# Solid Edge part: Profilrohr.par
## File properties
Username: ahadarics
Dokumentum tartalom típus: 0
Author: ahadarics
Last saved by: ahadarics
Revision: 78
Sűrűség: 0,000 kg/m^3
Pontosság: 0,990
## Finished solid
Body 1: solid body, 91 faces, 266 edges, 176 vertices.
  Faces by surface: plane 46, cylinder 45
  Edges by curve: line 176, circle 90
Bounding box of the edges (mm): 49.000 x 49.000 x 30.800, from (-24.5, -24.5, 0) to (24.5, 24.5, 30.8).
Cylindrical faces by radius (mm): R0.15 x20, R0.25 x20, R8 x4, R16 x1
Planar faces by outward normal: +x 11, +y 11, +z 1, -x 11, -y 11, -z 1
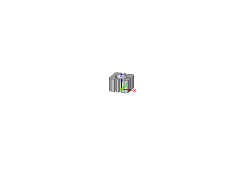
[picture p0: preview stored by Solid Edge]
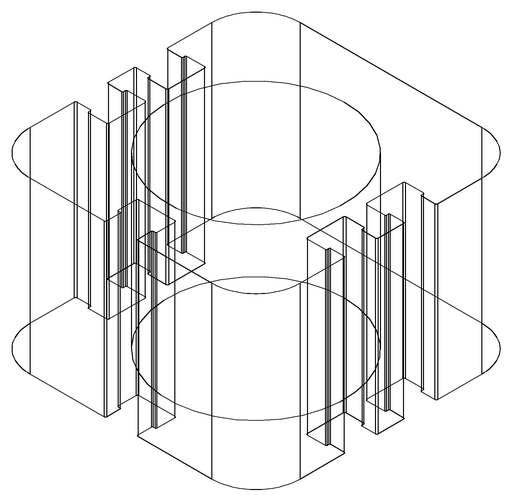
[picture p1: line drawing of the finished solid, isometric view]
